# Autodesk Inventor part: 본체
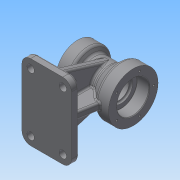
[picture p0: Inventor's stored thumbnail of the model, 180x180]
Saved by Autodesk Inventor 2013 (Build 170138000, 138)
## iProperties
Created: 2015-08
Part Number: 본체
Material: 일반
Document SubType Name: Modeling
Designer: Administrator
Density: 1 g/cm^3
Author: Administrator
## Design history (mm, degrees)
sketch "스케치1"
  geometry: L1 (0, 0)-(90, 0); L2 (0, 0)-(0, 35); L3 (0, 35)-(20, 35); L4 (20, 35)-(25.196, 26); L5 (25.196, 26)-(53.315, 26); L6 (53.315, 26)-(70, 40); L7 (70, 40)-(90, 40); L8 (90, 40)-(90, 0)
  constraints: 16 end point, 3 parallel, 2 perpendicular, 1 horizontal
  dimensions: "d0" = 90 distance of L1.start L1.end; "d1" = 20 distance of L2.end L3.end; "d3" = 70 diameter of L3 L1; "d4" = 80 diameter of L7 L1; "d5" = 40 deg angle of L5 L6; "d6" = 60 deg angle of L5 L4; "d7" = 20 distance of L6.end L7.end; "d8" = 52 diameter of L5 L1
revolve "회전1" sketch "스케치1" stored, may be unused: angle "d9" = 90 deg
sketch "스케치2"
  geometry: L1 (0, -78)-(80, -78); L2 (80, -78)-(80, -90); L3 (80, -90)-(0, -90); L4 (0, -90)-(0, -78); 1 further point
  constraints: 8 end point, 2 parallel, 1 horizontal, 1 perpendicular, 1 vertical alignment
  dimensions: "d10" = 12 distance of L1.end L2.end; "d12" = 80 distance of L2.end L3.end; "d13" = 90 distance from line of L3 point (0, 0)
extrude "돌출1" join sketch "스케치2" stored distance "d14" = 122; taper "d15" = 0 deg
sketch "스케치3"
  geometry: L1 (0, -35)-(0, 35) reference; L2 (0, 35)-(20, 35) reference; L3 (20, 35)-(25.196, 26) reference; L4 (25.196, 26)-(53.315, 26) reference; L5 (53.315, 26)-(70, 40) reference; L6 (70, 40)-(90, 40) reference; L7 (90, 40)-(90, -40) reference; L8 (90, -40)-(70, -40) reference; L9 (70, -40)-(53.315, -26) reference; L10 (53.315, -26)-(25.196, -26) reference; L11 (25.196, -26)-(20, -35) reference; L12 (20, -35)-(0, -35) reference; L13 (80, -78)-(80, -90) reference; L14 (80, -90)-(0, -90) reference; L15 (0, -90)-(0, -78) reference; L16 (0, -78)-(80, -78) reference; L17 (10, -78)-(10, -35); L18 (70, -78)-(76.7, -40); 1 further point
  constraints: 4 end point, 3 point on line, 1 midpoint
  dimensions: "d16" = 10 distance from line of L17 L15.end; "d19" = 80 deg angle of L16 L18; "d20" = 10 distance from line of L13 L18.start
  node "절단 모서리 투영1"
node "작업 평면1"
sketch "스케치4"
  geometry: L1 (-78, -61)-(-90, -61) reference; L2 (-90, -61)-(-90, 61) reference; L3 (-90, 61)-(-78, 61) reference; L4 (-78, 61)-(-78, -61) reference; L5 (7.592, 24.867)-(-78, 51); L6 (7.592, -24.867)-(-78, -51); A1 r 26 centre (0, 0) between (7.592, 24.867) and (7.592, -24.867) reference; 1 further point
  constraints: 4 end point, 2 point on circle, 2 point on line, 2 tangent
  dimensions: "d22" = 10 distance from line of L1 L6.end; "d23" = 10 distance from line of L3 L5.end
extrude "돌출2" join sketch "스케치4" stored distance "d24" = 12; taper "d25" = 0 deg
feature "리브1" dims "d26" = 1, "d27" = 12, "d28" = 0, "d29" = 0, "d30" = 1, "d31" = 1
feature "리브2" dims "d32" = 1, "d33" = 12, "d34" = 0, "d35" = 0, "d36" = 1, "d37" = 1
hole "구멍1" diameter "d40" = 38; stored, may be unused: countersink angle "d44" = 90 deg, drill point angle "d46" = 0 deg; dims "d41" = 6, "d42" = 52, "d43" = 20, "d45" = 23, "d47" = 10, "d48" = 10
hole "구멍2" diameter "d51" = 32; stored, may be unused: countersink angle "d55" = 90 deg, drill point angle "d57" = 118 deg; dims "d49" = 10, "d50" = 10, "d52" = 6, "d53" = 40, "d54" = 17, "d56" = 23
sketch "스케치5"
  geometry: C1 r 26 at (0, 0) reference; 1 further point
  constraints: 1 vertical alignment
  dimensions: "d58" = 33 distance of C1.centre point (0, 33)
hole "구멍3" sketch "스케치5" at (0, 33) diameter "d59" = 3.242; stored, may be unused: countersink angle "d63" = 90 deg, drill point angle "d65" = 118 deg; dims "d60" = 10, "d61" = 40, "d62" = 17, "d64" = 13
sketch "스케치6"
  geometry: C1 r 20 at (0, 0) reference; 1 further point
  constraints: 1 vertical alignment
  dimensions: "d69" = 27 distance of C1.centre point (0, 27)
hole "구멍4" sketch "스케치6" at (0, 27) diameter "d70" = 3.242; stored, may be unused: countersink angle "d74" = 90 deg, drill point angle "d76" = 118 deg; dims "d71" = 10, "d72" = 40, "d73" = 17, "d75" = 13
sketch "스케치7"
  geometry: L1 (6, -25.298)-(6, -78) reference; L2 (51, -78)-(6, -78) reference; L3 (-61, -78)-(-51, -78) reference; L4 (-51, -78)-(-6, -78) reference; L5 (-6, -78)-(-6, -25.298) reference; L6 (-51, -78)-(-24.867, 7.592) reference; L7 (-61, -90)-(-61, -78) reference; L8 (61, -90)-(-61, -90) reference; L9 (61, -78)-(61, -90) reference; L10 (51, -78)-(61, -78) reference; L11 (6, -78)-(51, -78) reference; L12 (6, -25.298)-(6, -78) reference; L13 (24.867, 7.592)-(51, -78) reference; L14 (18, -54)-(18, -60); L15 (30, -54)-(30, -60); C1 r 16 at (0, 0) reference; A1 r 26 centre (0, 0) between (-24.867, 7.592) and (-6, -25.298) reference; A2 r 26 centre (0, 0) between (6, -25.298) and (24.867, 7.592) reference; A3 r 26 centre (0, 0) between (24.867, 7.592) and (-24.867, 7.592) reference; A4 r 6 centre (24, -54) between (30, -54) and (18, -54); A5 r 6 centre (24, -60) between (18, -60) and (30, -60)
  constraints: 4 end point, 4 point on circle, 3 tangent, 2 centre point, 1 parallel, 1 vertical alignment
  dimensions: "d80" = 12 diameter of A4; "d81" = 12 diameter of A5; "d82" = 18 dimension on A5 A4; "d83" = 18 distance from line of A5.centre L2; "d84" = 24 horizontal distance of A5.centre C1.centre
extrude "돌출3" cut sketch "스케치7" stored distance "d85" = 12; taper "d86" = 0 deg
fillet "모깎기1" dims "d87" = 14
sketch "스케치8"
  geometry: C1 r 6 at (52, 14); C2 r 6 at (0, 14); C3 r 6 at (0, 108); C4 r 6 at (52, 108); A1 r 14 centre (0, 14) between (-14, 14) and (0, 0) reference; A2 r 14 centre (52, 14) between (52, 0) and (66, 14) reference; A3 r 14 centre (52, 108) between (66, 108) and (52, 122) reference; A4 r 14 centre (0, 108) between (0, 122) and (-14, 108) reference; 1 further point
  constraints: 4 centre point, 4 coincident
  dimensions: "d88" = 12 diameter of C1; "d90" = 12 diameter of C2; "d91" = 12 diameter of C3; "d92" = 12 diameter of C4
extrude "돌출4" cut sketch "스케치8" stored distance "d93" = 12; taper "d94" = 0 deg
sketch "스케치9"
  geometry: L1 (0, 0)-(0, 43.518) reference; L2 (-10, 0)-(4, 0) reference; L3 (-10, -12)-(-10, 0) reference; 2 further points
  constraints: 1 other
  dimensions: "d95" = 24 distance from line of point (16, 24) L2; "d97" = 16 distance from line of point (16, 24) L1
feature "엠보싱1" sketch "스케치9" dims "d0" = 90, "d1" = 20, "d3" = 70, "d4" = 80, "d5" = 40 deg, "d6" = 60 deg, "d7" = 20, "d8" = 52, "d98" = 0.5, "d99" = 0
fillet "모깎기2" dims "d100" = 5
fillet "모깎기3" dims "d101" = 0.3
fillet "모깎기4" dims "d102" = 3
chamfer "모따기1" distance "d103" = 1; stored, may be unused: second distance "d104" = 2, angle "d105" = 45 deg
fillet "모깎기5" dims "d106" = 3
fillet "모깎기6" dims "d107" = 3
fillet "모깎기7" dims "d108" = 3
fillet "모깎기8" dims "d109" = 3
node "솔리드1"
pattern_circular "원형 패턴1" dims angle "d67" = 360 deg
pattern_circular "원형 패턴2" dims angle "d78" = 360 deg
mirror "대칭1"
node "작업 평면2"
node "절단 모서리 투영2"
node "절단 모서리 투영3"
